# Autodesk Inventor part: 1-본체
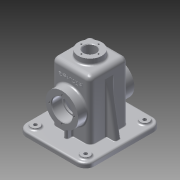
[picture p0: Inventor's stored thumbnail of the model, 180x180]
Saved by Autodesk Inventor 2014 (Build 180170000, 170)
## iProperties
Created: 2015-12
Part Number: 1-본체
Material: 알루미늄 6061
Document SubType Name: Modeling
Designer: Administrator
Density: 2.71 g/cm^3
Appearance: 알루미늄 - 평지
Mass: 806.058 g
Surface Area: 909.941 cm^2
Volume: 297.438 cm^3
Author: Administrator
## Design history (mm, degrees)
sketch "스케치1"
  geometry: L1 (-57.5, -65)-(57.5, -65); L2 (57.5, -65)-(57.5, 65); L3 (57.5, 65)-(-57.5, 65); L4 (-57.5, 65)-(-57.5, -65); L5 (-57.5, -65)-(57.5, 65); L6 (57.5, -65)-(-57.5, 65); L7 (-27.5, -27.5)-(27.5, -27.5); L8 (27.5, -27.5)-(27.5, 27.5); L9 (27.5, 27.5)-(-27.5, 27.5); L10 (-27.5, 27.5)-(-27.5, -27.5); L11 (-27.5, -27.5)-(27.5, 27.5); L12 (27.5, -27.5)-(-27.5, 27.5); 1 further point
  constraints: 24 end point, 4 midpoint, 4 parallel, 2 horizontal, 2 perpendicular
  dimensions: "d0" = 115 distance of L3.end L2.end; "d1" = 130 distance of L2.end L1.end; "d4" = 55 distance of L9.end L8.end; "d5" = 55 distance of L8.end L7.end
extrude "돌출1" new body sketch "스케치1" distance "d2" = 8; taper "d3" = 0 deg
sketch "스케치2"
  geometry: L1 (32.5, -32.5)-(-32.5, -32.5); L2 (-32.5, -32.5)-(-32.5, 32.5); L3 (-32.5, 32.5)-(32.5, 32.5); L4 (32.5, 32.5)-(32.5, -32.5); L5 (32.5, -32.5)-(-32.5, 32.5); L6 (-32.5, -32.5)-(32.5, 32.5); 1 further point
  constraints: 12 end point, 2 midpoint, 2 parallel, 1 horizontal, 1 perpendicular
  dimensions: "d6" = 65 distance of L2.end L3.end; "d7" = 65 distance of L1.end L2.end
extrude "돌출2" join sketch "스케치2" distance "d8" = 100; taper "d9" = 0 deg
sketch "스케치5"
  geometry: C1 r 10.5 at (0, 0); 1 further point
  constraints: 1 centre point, 1 coincident
  dimensions: "d13" = 21 diameter of C1
extrude "돌출4" cut sketch "스케치5" stored distance "d14" = 2; taper "d15" = 0 deg
sketch "스케치6"
  geometry: C1 r 10.5 at (0, 0) reference; C2 r 20 at (0, 0)
  constraints: 1 centre point, 1 coincident
  dimensions: "d16" = 40 diameter of C2
extrude "돌출5" join sketch "스케치6" distance "d17" = 10; taper "d18" = 0 deg
sketch "스케치7"
  geometry: L1 (-32.5, -32.5)-(32.5, -32.5) reference; L2 (-32.5, 32.5)-(-32.5, -32.5) reference; C1 r 20 at (0, 0) reference; A1 r 14.5 centre (0, 0) between (0, 14.5) and (14.5, 0); 2 further points
  constraints: 4 point on circle, 1 centre point, 1 coincident
  dimensions: "d19" = 29 diameter of A1; "d20" = 20.5061 distance of A1.end A1.start; "d21" = 20.5061 distance of A1.end point (0, -14.5); "d22" = 29 distance of A1.end point (-14.5, 0); "d23" = 47 distance from line of A1.end L2
hole "구멍1" sketch "스케치7" at (0, 14.5), (14.5, 0), (-14.5, 0), (0, -14.5) diameter "d24" = 2.459; stored, may be unused: countersink angle "d28" = 90 deg, drill point angle "d30" = 118 deg; dims "d25" = 7, "d26" = 4, "d27" = 2, "d29" = 9
sketch "스케치8"
  geometry: L1 (-32.5, -32.5)-(-32.5, 32.5) reference; L2 (-32.5, 32.5)-(32.5, 32.5) reference; L3 (32.5, 32.5)-(32.5, -32.5) reference; L4 (32.5, -32.5)-(-32.5, -32.5) reference; L5 (-57.5, -65)-(-57.5, 65) reference; L6 (-57.5, 65)-(57.5, 65) reference; L7 (57.5, 65)-(57.5, -65) reference; L8 (57.5, -65)-(-57.5, -65) reference; C1 r 3 at (-42.5, 50); C2 r 10.5 at (0, 0) reference; C3 r 3 at (-42.5, -50); C4 r 3 at (42.5, -50); C5 r 3 at (42.5, 50); 1 further point
  constraints: 4 centre point
  dimensions: "d31" = 6 diameter of C1; "d124" = 15 distance from line of L5 C1.centre; "d125" = 15 distance from line of L6 C1.centre; "d126" = 6 diameter of C3; "d127" = 6 diameter of C4; "d128" = 6 diameter of C5; "d129" = 100 distance of C3.centre C1.centre; "d130" = 85 distance of C3.centre C4.centre; "d131" = 100 distance of C5.centre C4.centre; "d132" = 15 distance from line of L7 C5.centre; "d133" = 15 distance from line of L6 C5.centre; "d134" = 15 distance from line of L7 C4.centre
  node "절단 모서리 투영7"
fillet "모깎기1" dims "d48" = 15
sketch "스케치10"
  geometry: L1 (0, 0)-(0, 100) reference; L2 (32.5, -8)-(32.5, 45); C1 r 27.5 at (32.5, 45)
  constraints: 2 end point, 1 centre point, 1 coincident, 1 parallel
  dimensions: "d50" = 53 distance of L2.start L2.end; "d51" = 55 diameter of C1
extrude "돌출8" join sketch "스케치10" distance "d52" = 15; taper "d53" = 0 deg
sketch "스케치11"
  geometry: L1 (-32.5, 55)-(32.5, 55) reference; L2 (20, 65)-(-20, 65) reference; C1 r 27.5 at (0, 0) reference; A1 r 21 centre (0, 0) between (0, 21) and (21, 0); 3 further points
  constraints: 4 point on circle, 1 centre point, 1 coincident
  dimensions: "d54" = 42 diameter of A1; "d55" = 63 dimension on A1.end L2; "d56" = 42 dimension on A1.start L2; "d57" = 84 dimension on point (0, -21) L2; "d58" = 63 dimension on point (-21, 0) L2
hole "구멍2" sketch "스케치11" at (0, 21), (21, 0), (0, -21), (-21, 0) diameter "d59" = 3.242; stored, may be unused: countersink angle "d63" = 90 deg, drill point angle "d65" = 118 deg; dims "d60" = 8, "d61" = 4, "d62" = 2, "d64" = 10
sketch "스케치12"
  geometry: C1 r 27.5 at (0, 0) reference; C2 r 17.5 at (0, 0); 1 further point
  constraints: 1 centre point, 1 coincident
  dimensions: "d66" = 35 diameter of C2
extrude "돌출9" cut sketch "스케치12" distance "d67" = 17; taper "d68" = 0 deg
sketch "스케치13"
  geometry: C1 r 17.5 at (0, 0) reference; C2 r 15 at (0, 0); 1 further point
  constraints: 1 centre point, 1 coincident
  dimensions: "d69" = 30 diameter of C2
extrude "돌출10" cut sketch "스케치13" distance "d70" = 3; taper "d71" = 0 deg
fillet "모깎기3" dims "d76" = 8
sketch "스케치25"
  geometry: L1 (10.5, 0)-(10.5, 118) reference; L2 (10.5, 118)-(13.271, 118) reference; L3 (13.271, 118)-(13.271, 109) reference; L4 (13.271, 109)-(14.5, 108.261) reference; L5 (14.5, 108.261)-(15.73, 109) reference; L6 (15.73, 109)-(15.73, 118) reference; L7 (15.73, 118)-(20, 118) reference; L8 (20, 118)-(20, 108) reference; L9 (20, 108)-(24.5, 108) reference; L10 (32.5, 100)-(32.5, 8) reference; L11 (32.5, 8)-(57.5, 8) reference; L12 (57.5, 8)-(57.5, 0) reference; L13 (57.5, 0)-(10.5, 0) reference; L14 (-10.5, 118)-(-10.5, 0) reference; L15 (-10.5, 0)-(-57.5, 0) reference; L16 (-57.5, 8)-(-32.5, 8) reference; L17 (-32.5, 8)-(-32.5, 100) reference; L18 (-24.5, 108)-(-20, 108) reference; L19 (-20, 108)-(-20, 118) reference; L20 (-20, 118)-(-15.73, 118) reference; L21 (-15.73, 118)-(-15.73, 109) reference; L22 (-15.73, 109)-(-14.5, 108.261) reference; L23 (-14.5, 108.261)-(-13.271, 109) reference; L24 (-13.271, 109)-(-13.271, 118) reference; L25 (-13.271, 118)-(-10.5, 118) reference; L26 (57.5, 8)-(47.5, 8); L27 (47.5, 8)-(30.6, 103.845); L28 (-57.5, 0)-(-57.5, 8) reference; A1 r 8 centre (24.5, 100) between (32.5, 100) and (24.5, 108) reference; A2 r 8 centre (-24.5, 100) between (-24.5, 108) and (-32.5, 100) reference; 1 further point
  constraints: 4 end point, 1 point on line
  dimensions: "d92" = 10 distance of L11.end L26.end; "d93" = 10 deg angle of L12 L27
  node "절단 모서리 투영3"
fillet "모깎기5" dims "d94" = 0.3
sketch "스케치29"
  geometry: L1 (57.5, 8)-(57.5, 0) reference; L2 (57.5, 8)-(47.5, 8); L3 (-57.5, 0)-(-57.5, 8) reference; L4 (10.5, 0)-(10.5, 118) reference; L5 (10.5, 118)-(13.271, 118) reference; L6 (13.271, 118)-(13.271, 109) reference; L7 (13.271, 109)-(14.5, 108.261) reference; L8 (14.5, 108.261)-(15.73, 109) reference; L9 (15.73, 109)-(15.73, 118) reference; L10 (15.73, 118)-(20, 118) reference; L11 (20, 118)-(20, 108) reference; L12 (20, 108)-(24.5, 108) reference; L13 (32.5, 100)-(32.5, 8) reference; L14 (32.5, 8)-(57.5, 8) reference; L15 (57.5, 8)-(57.5, 0) reference; L16 (57.5, 0)-(10.5, 0) reference; L17 (-10.5, 118)-(-10.5, 0) reference; L18 (-10.5, 0)-(-57.5, 0) reference; L19 (-57.5, 0)-(-57.5, 8) reference; L20 (-57.5, 8)-(-32.5, 8) reference; L21 (-32.5, 8)-(-32.5, 100) reference; L22 (-24.5, 108)-(-20, 108) reference; L23 (-20, 108)-(-20, 118) reference; L24 (-20, 118)-(-15.73, 118) reference; L25 (-15.73, 118)-(-15.73, 109) reference; L26 (-15.73, 109)-(-14.5, 108.261) reference; L27 (-14.5, 108.261)-(-13.271, 109) reference; L28 (-13.271, 109)-(-13.271, 118) reference; L29 (-13.271, 118)-(-10.5, 118) reference; L30 (47.5, 8)-(32.5, 93.069); A1 r 8 centre (24.5, 100) between (32.5, 100) and (24.5, 108) reference; A2 r 8 centre (-24.5, 100) between (-24.5, 108) and (-32.5, 100) reference; 1 further point
  constraints: 4 end point, 1 perpendicular, 1 point on line
  dimensions: "d119" = 10 distance of L1.start L2.end; "d121" = 10 deg angle of L15 L30
extrude "돌출17" join sketch "스케치29" stored distance "d122" = 10; taper "d123" = 0 deg
extrude "돌출18" cut sketch "스케치8" distance "d135" = 10; taper "d136" = 0 deg
sketch "스케치31"
  geometry: C1 r 3 at (42.5, -50) reference; C2 r 3 at (-42.5, 50) reference; C3 r 3 at (-42.5, -50) reference; C4 r 3 at (42.5, 50) reference; C5 r 7.5 at (42.5, 50); C6 r 7.5 at (42.5, -50); C7 r 7.5 at (-42.5, -50); C8 r 7.5 at (-42.5, 50); A1 r 15 centre (42.5, 50) between (57.5, 50) and (42.5, 65) reference; A2 r 15 centre (-42.5, 50) between (-42.5, 65) and (-57.5, 50) reference; A3 r 15 centre (-42.5, -50) between (-57.5, -50) and (-42.5, -65) reference; A4 r 15 centre (42.5, -50) between (42.5, -65) and (57.5, -50) reference; 1 further point
  constraints: 4 centre point, 4 coincident
  dimensions: "d137" = 15 diameter of C5; "d138" = 15 diameter of C6; "d139" = 15 diameter of C7; "d140" = 15 diameter of C8
extrude "돌출19" join sketch "스케치31" distance "d141" = 3; taper "d142" = 0 deg
fillet "모깎기6" dims "d143" = 3
fillet "모깎기7" dims "d144" = 8
fillet "모깎기8" dims "d145" = 3
chamfer "모따기1" distance "d147" = 1; stored, may be unused: second distance "d148" = 2, angle "d149" = 45 deg
chamfer "모따기2" distance "d152" = 1; stored, may be unused: second distance "d153" = 2, angle "d154" = 45 deg
sketch "스케치32"
  geometry: L1 (-8, 0)-(-8, -92) reference; L2 (49, 8)-(0, 8) reference; L3 (44.5, 18)-(4.5, 18) reference; 3 further points
  constraints: 1 other
  dimensions: "d186" = 28 distance from line of point (24.5, -10) L3; "d187" = 32.5 distance from line of point (24.5, -10) L1
sketch "스케치34"
  geometry: L1 (42.5, -60)-(-42.5, -60); L2 (-52.5, -50)-(-52.5, 50); L3 (-42.5, 60)-(42.5, 60); L4 (52.5, 50)-(52.5, -50); L5 (52.5, -60)-(-52.5, 60); L6 (-52.5, -60)-(52.5, 60); C1 r 3 at (-42.5, -50) reference; C2 r 3 at (42.5, 50) reference; C3 r 3 at (42.5, -50) reference; C4 r 3 at (-42.5, 50) reference; C5 r 10.5 at (0, 0) reference; A1 r 10 centre (-42.5, 50) between (-42.5, 60) and (-52.5, 50); A2 r 10 centre (42.5, 50) between (52.5, 50) and (42.5, 60); A3 r 10 centre (42.5, -50) between (42.5, -60) and (52.5, -50); A4 r 10 centre (-42.5, -50) between (-52.5, -50) and (-42.5, -60)
  constraints: 12 end point, 8 point on circle, 8 point on line, 8 tangent, 4 centre point, 3 equal radius, 2 midpoint, 2 parallel, 1 horizontal, 1 perpendicular
  dimensions: "d170" = 105 distance of L5.end L6.end; "d171" = 120 distance of L6.start L5.end; "d172" = 10 radius of A1
extrude "돌출21" join sketch "스케치34" distance "d173" = 2; taper "d174" = 0 deg
sketch "스케치35"
  geometry: L1 (27.5, -27.5)-(-27.5, -27.5); L2 (-27.5, -27.5)-(-27.5, 27.5); L3 (-27.5, 27.5)-(27.5, 27.5); L4 (27.5, 27.5)-(27.5, -27.5); L5 (27.5, -27.5)-(-27.5, 27.5); L6 (-27.5, -27.5)-(27.5, 27.5); C1 r 10.5 at (0, 0) reference
  constraints: 12 end point, 2 midpoint, 2 parallel, 1 horizontal, 1 perpendicular
  dimensions: "d175" = 55 distance of L2.end L3.end; "d176" = 55 distance of L1.end L2.end
extrude "돌출22" cut sketch "스케치35" distance "d177" = 105; taper "d178" = 0 deg
fillet "모깎기18" dims "d179" = 3
fillet "모깎기19" dims "d180" = 3
sketch "스케치36"
  geometry: L1 (27.5, -2)-(27.5, 100) reference; L2 (65, 5)-(65, 0) reference; L3 (-50, 8)-(50, 8) reference; L4 (27.5, 8)-(42.5, 8); L5 (42.5, 8)-(42.5, 31.676); L6 (42.5, 31.676)-(27.5, 31.676); 1 further point
  constraints: 6 end point, 4 point on line, 2 perpendicular
  dimensions: "d181" = 15 distance of L4.start L4.end; "d182" = 23.6761 distance between parallel lines of L3 L6
extrude "돌출23" join sketch "스케치36" stored distance "d183" = 6; taper "d184" = 0 deg
feature "엠보싱2" dims "d188" = 0.5, "d189" = 0
fillet "모깎기26" dims "d195" = 3
fillet "모깎기27" dims "d196" = 3
fillet "모깎기28" dims "d197" = 1
fillet "모깎기25" dims "d194" = 1
node "솔리드1"
mirror "대칭1"
mirror "대칭2"
mirror "대칭3"
mirror "대칭4"
node "작업 평면1"
node "절단 모서리 투영6"
other parameters: "d120" = 10 deg
